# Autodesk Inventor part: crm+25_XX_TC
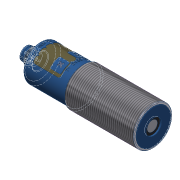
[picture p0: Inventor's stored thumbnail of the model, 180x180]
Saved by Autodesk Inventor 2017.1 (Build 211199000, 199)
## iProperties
Shininess: 20.0
Length Units: 11269
Angle Units: 11279
Time Units: 11290
Mass Units: 11283
Length Display Precision: 2
Angle Display Precision: 2
Company: Microsonic
Part Number: crm+25_XX_TC
Material: ABS Plastik
Document SubType Name: Modellieren
Description: mic+ 25 Sensor
Checked By: Alves
Created: 2005-08
Designer: Ohle
Manufacturer: Standard
Standards Organization: Custom
Appearance: Blau (himmelsblau)
Density: 0.0
Volumn: 0.0
Area: 0.0
PropertySet Name: Model Information
Control State: 0
Master: False
Checked Out: False
BESTELLNUMMER: mic+25/XX/TC
ME: ST
Title: mic+ 25 Sensor
Author: Ohle
Comments: keine Bemerkung
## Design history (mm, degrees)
revolve "Grundkörper" stored, may be unused: angle "d14" = 90 deg
workplane "Arbeitsebene1"
feature "Gewinde M30x1,5" dims "d79" = 10, "d80" = 0
feature "Gewinde M12x1" dims "d85" = 10, "d86" = 0
sketch "Skizze8"
  geometry: L1 (-94.032, 0)-(15.672, 0) reference; L2 (0, -19.965)-(0, 19.965) reference; L3 (-76.7, -13.9)-(-58.24, -13.9); L4 (-56.5, -12.16)-(-56.5, -3.843); L5 (-56.5, 3.843)-(-56.5, 12.16); L6 (-58.24, 13.9)-(-76.26, 13.9); L7 (-64.7, -11.7)-(-58.3, -11.7); L8 (-57.3, -10.7)-(-57.3, -3.9); L9 (-58.3, -2.9)-(-64.7, -2.9); L10 (-65.7, -3.9)-(-65.7, -10.7); L11 (-57.3, 4)-(-57.3, 10.7); L12 (-58.3, 11.7)-(-64.7, 11.7); L13 (-65.7, 10.7)-(-65.7, 4); L14 (-58, 2.107)-(-56.853, 3.081); L15 (-58, -2.1)-(-56.85, -3.083); L16 (-78, 12.16)-(-78, 5.023); L17 (-78, 1.577)-(-78, -0.577); L18 (-58.3, 3)-(-64.7, 3); L19 (-78, -4.023)-(-78, -6.827); L20 (-78, -10.273)-(-78, -12.6); L21 (-56.5, 0.383)-(-56.5, -0.377); A1 r 1.74 centre (-58.24, -12.16) between (-58.24, -13.9) and (-56.5, -12.16); A2 r 1.74 centre (-58.24, 12.16) between (-56.5, 12.16) and (-58.24, 13.9); A3 r 1.74 centre (-76.26, 12.16) between (-76.26, 13.9) and (-78, 12.16); A4 r 1 centre (-64.7, -3.9) between (-64.7, -2.9) and (-65.7, -3.9); A5 r 1 centre (-58.3, -3.9) between (-57.3, -3.9) and (-58.3, -2.9); A6 r 1 centre (-64.7, -10.7) between (-65.7, -10.7) and (-64.7, -11.7); A7 r 1 centre (-58.3, -10.7) between (-58.3, -11.7) and (-57.3, -10.7); A8 r 1 centre (-64.7, 4) between (-65.7, 4) and (-64.7, 3); A9 r 1 centre (-64.7, 10.7) between (-64.7, 11.7) and (-65.7, 10.7); A10 r 1 centre (-58.3, 4) between (-58.3, 3) and (-57.3, 4); A11 r 1 centre (-58.3, 10.7) between (-57.3, 10.7) and (-58.3, 11.7); A12 r 1 centre (-57.5, -3.843) between (-56.5, -3.843) and (-56.85, -3.083); A13 r 1 centre (-57.5, 3.843) between (-56.853, 3.081) and (-56.5, 3.843); A14 r 1.74 centre (-76.26, 5.023) between (-78, 5.023) and (-76.5, 3.3); A15 r 1.74 centre (-76.26, -10.273) between (-76.5, -8.55) and (-78, -10.273); A16 r 1.74 centre (-76.26, -6.827) between (-78, -6.827) and (-76.5, -8.55); A17 r 1.74 centre (-76.26, 1.577) between (-76.5, 3.3) and (-78, 1.577); A18 r 1.74 centre (-76.26, -0.577) between (-78, -0.577) and (-76.5, -2.3); A19 r 1.74 centre (-76.26, -4.023) between (-76.5, -2.3) and (-78, -4.023); A20 r 1.3 centre (-76.7, -12.6) between (-78, -12.6) and (-76.7, -13.9); A21 r 1.74 centre (-58.24, 0.383) between (-59.938, 0.003) and (-59.937, 0); A22 r 1.74 centre (-58.24, -0.377) between (-59.938, 0.003) and (-59.939, 0); A23 r 1.74 centre (-58.24, -0.377) between (-58, -2.1) and (-56.5, -0.377); A24 r 1.74 centre (-58.24, -0.377) between (-56.541, 0) and (-56.542, 0.003); A25 r 1.74 centre (-58.24, 0.383) between (-56.543, 0) and (-56.542, 0.003); A26 r 1.74 centre (-58.24, 0.383) between (-56.5, 0.383) and (-58, 2.107); 6 further points
  constraints: 52 point on circle, 38 end point, 37 tangent, 26 centre point, 14 point on line, 13 equal radius, 11 vertical alignment, 5 collinear, 5 horizontal alignment, 5 perpendicular, 4 parallel, 3 horizontal
  dimensions: "d98" = 56.5 distance between parallel lines of L2 L4; "d102" = 8.4 distance of point (-65.7, -11.7) point (-57.3, -11.7); "d103" = 9.2 distance between parallel lines of L10 L4; "d104" = 8.8 distance of point (-65.7, -2.9) point (-65.7, -11.7); "d105" = 2.9 distance between parallel lines of L1 L9; "d258" = 1 radius of A4; "d445" = 2.1 vertical distance of point (0, 0) L15.start; "d448" = 1 radius of A13; "d450" = 58 horizontal distance of point (0, 0) L14.start; "d452" = 21.5 distance between parallel lines of L16 L5; "d453" = 1.74 radius of A14; "d594" = 1.5 distance from line of L16 A14.end; "d596" = 3 distance from line of point (0, 0) L18; "d597" = 8.7 distance between parallel lines of L18 L12; "d619" = 13.9 distance from line of L3 point (0, 0); "d625" = 13.9 distance from line of point (0, 0) L6; "d630" = 3.3 vertical distance of point (0, 0) A14.end; "d644" = 5.35 distance from line of A15.start L3; "d645" = 1.3 radius of A20; "d782" = 2.3 vertical distance of A18.end point (0, 0); "d1000" = 49.4633 deg angle of L15 L2; "d1002" = 2.10658 distance from line of L1 L14.start; "d1003" = 1.74 radius of A26; "d1004" = 1.74 radius of A23; "d1005" = 1.74 radius of A25; "d1006" = 1.74 radius of A24
feature "Prägung Anzeige" sketch "Skizze8" dims "d4" = 11, "d9" = 15, "d10" = 14, "d11" = 6, "d12" = 5, "d32" = 1, "d33" = 1 (= d32), "d37" = 0.3, "d38" = 55.5, "d87" = 2, "d387" = 6, "d388" = 45 deg, "d389" = 13.5, "d390" = 0.5, "d391" = 0.5, "d396" = 45 deg, "d397" = 0.5, "d398" = 7.2, "d400" = 2, "d401" = 30 deg, "d402" = 5.175, "d403" = 0.2, "d404" = 1, "d405" = 10 deg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
feature "Prägung T1" dims "d4" = 11, "d9" = 15, "d10" = 14, "d11" = 6, "d12" = 5, "d32" = 1, "d33" = 1 (= d32), "d37" = 0.3, "d38" = 55.5, "d87" = 2, "d166" = 0.2, "d167" = 0, "d387" = 6, "d388" = 45 deg, "d389" = 13.5, "d390" = 0.5, "d391" = 0.5, "d396" = 45 deg, "d397" = 0.5, "d398" = 7.2, "d400" = 2, "d401" = 30 deg, "d402" = 5.175, "d403" = 0.2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
feature "Prägung D1" dims "d4" = 11, "d9" = 15, "d10" = 14, "d11" = 6, "d12" = 5, "d32" = 1, "d33" = 1 (= d32), "d37" = 0.3, "d38" = 55.5, "d87" = 2, "d387" = 6, "d388" = 45 deg, "d389" = 13.5, "d390" = 0.5, "d391" = 0.5, "d396" = 45 deg, "d397" = 0.5, "d398" = 7.2, "d400" = 2, "d401" = 30 deg, "d402" = 5.175, "d403" = 0.2, "d404" = 1, "d405" = 10 deg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
feature "Prägung D2" dims "d4" = 11, "d9" = 15, "d10" = 14, "d11" = 6, "d12" = 5, "d32" = 1, "d33" = 1 (= d32), "d37" = 0.3, "d38" = 55.5, "d87" = 2, "d387" = 6, "d388" = 45 deg, "d389" = 13.5, "d390" = 0.5, "d391" = 0.5, "d396" = 45 deg, "d397" = 0.5, "d398" = 7.2, "d400" = 2, "d401" = 30 deg, "d402" = 5.175, "d403" = 0.2, "d404" = 1, "d405" = 10 deg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
feature "Prägung T2" dims "d4" = 11, "d9" = 15, "d10" = 14, "d11" = 6, "d12" = 5, "d32" = 1, "d33" = 1 (= d32), "d37" = 0.3, "d38" = 55.5, "d87" = 2, "d387" = 6, "d388" = 45 deg, "d389" = 13.5, "d390" = 0.5, "d391" = 0.5, "d396" = 45 deg, "d397" = 0.5, "d398" = 7.2, "d400" = 2, "d401" = 30 deg, "d402" = 5.175, "d403" = 0.2, "d404" = 1, "d405" = 10 deg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
feature "Prägung cm mm" dims "d4" = 11, "d9" = 15, "d10" = 14, "d11" = 6, "d12" = 5, "d32" = 1, "d33" = 1 (= d32), "d37" = 0.3, "d38" = 55.5, "d87" = 2, "d387" = 6, "d388" = 45 deg, "d389" = 13.5, "d390" = 0.5, "d391" = 0.5, "d396" = 45 deg, "d397" = 0.5, "d398" = 7.2, "d400" = 2, "d401" = 30 deg, "d402" = 5.175, "d403" = 0.2, "d404" = 1, "d405" = 10 deg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
sketch "Skizze21" dims "d962" = 0.2, "d963" = 0.15, "d964" = 0.15, "d965" = 0.2, "d966" = 0.2, "d967" = 0.2
  geometry: L1 (-79, 2.922)-(-79, 3.135); L2 (-79, 3.135)-(-81, 3.863); L3 (-81, 3.863)-(-81, 3.65); L4 (-81, 3.65)-(-79, 2.922); 3 further points; 2 other entities
  constraints: 8 end point, 3 parallel, 2 vertical, 4 other
  dimensions: "d959" = 0.2 distance between parallel lines of L2 L4; "d960" = 2 horizontal distance of L2.end L1.end; "d961" = 70 deg angle of L4 L1; "d968" = 1 horizontal distance of point (-80.5, 2.5) point (-79.5, 4.2); "d969" = 0.5 distance from line of point (-80.5, 2.5) L3; "d970" = 1.7 vertical distance of point (-79.5, 4.2) point (-80.5, 2.5); "d971" = 1.15 vertical distance of point (-80.5, 2.5) L3.end; "d972" = 81 horizontal distance of point (0, 0) L2.end; "d973" = 2.5 vertical distance of point (0, 0) point (-80.5, 2.5)
feature "Prägung %" sketch "Skizze21" dims "d4" = 11, "d9" = 15, "d10" = 14, "d11" = 6, "d12" = 5, "d32" = 1, "d33" = 1 (= d32), "d37" = 0.3, "d38" = 55.5, "d87" = 2, "d387" = 6, "d388" = 45 deg, "d389" = 13.5, "d390" = 0.5, "d391" = 0.5, "d396" = 45 deg, "d397" = 0.5, "d398" = 7.2, "d400" = 2, "d401" = 30 deg, "d402" = 5.175, "d403" = 0.2, "d404" = 1, "d405" = 10 deg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
feature "Prägung X" dims "d4" = 11, "d9" = 15, "d10" = 14, "d11" = 6, "d12" = 5, "d32" = 1, "d33" = 1 (= d32), "d37" = 0.3, "d38" = 55.5, "d87" = 2, "d202" = 0.2, "d203" = 0, "d387" = 6, "d388" = 45 deg, "d389" = 13.5, "d390" = 0.5, "d391" = 0.5, "d396" = 45 deg, "d397" = 0.5, "d398" = 7.2, "d400" = 2, "d401" = 30 deg, "d402" = 5.175, "d403" = 0.2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
sketch "Skizze13"
  geometry: C1 r 4.999 at (0, 0) reference; 1 further point
hole "Bohrung1" sketch "Skizze13" at (0, 0) diameter "d267" = 9; stored, may be unused: countersink angle "d271" = 82 deg, drill point angle "d273" = 0 deg; dims "d268" = 6, "d269" = 4, "d270" = 2, "d272" = 8
sketch "Skizze14"
  geometry: L1 (-3.606, -3.606)-(3.692, 3.692); L2 (-3.873, 3.873)-(3.971, -3.971); L3 (0, -21)-(0, 21) reference; C1 r 0.75 at (0, 0); C2 r 0.75 at (2.121, -2.121); C3 r 0.75 at (2.121, 2.121); C4 r 0.75 at (-2.121, 2.121); C5 r 0.75 at (-2.121, -2.121); A1 r 3 centre (0, 0) between (-2.121, 2.121) and (2.121, 2.121); 1 further point
  constraints: 6 centre point, 6 point on line, 4 end point, 4 equal radius, 4 point on circle, 2 coincident
  dimensions: "d282" = 1.5 diameter of C4; "d283" = 6 diameter of A1; "d284" = 45 deg angle of L2 L3; "d285" = 45 deg angle of L3 L1
extrude "Pole" join sketch "Skizze14" distance "d286" = 7; taper "d287" = 0 deg
fillet "Abrundung Pole" dims "d288" = 0.75
sketch "Skizze15"
  geometry: L1 (0, -21)-(0, 21) reference; A1 r 4.5 centre (0, 0) between (4.472, -0.499) and (4.472, 0.499); A2 r 4.5 centre (0, 0) between (0, -4.5) and (0.499, -4.472) reference; A3 r 0.5 centre (0, -4.5) between (0.499, -4.472) and (-0.499, -4.472); 1 further point
  constraints: 7 point on circle, 2 centre point, 1 coincident, 1 point on line
  dimensions: "d289" = 9 diameter of A1; "d345" = 1 diameter of A3
extrude "Verdrehsicherung" join sketch "Skizze15" distance "d291" = 8; taper "d292" = 0 deg
fillet "Rundung2" dims "d1094" = 0.1
node "Volumenkörper1"
node "Volumenkörper"
node "Flächenkörper"
sketch "Skizze2"
  geometry: L1 (-114.412, 0)-(24.975, 0) reference; L2 (5, -3)-(5, 18); L3 (-94.5, 0)-(-94.5, 4.999) reference; L4 (-92.5, 5)-(-91.277, 5); L5 (-90.7, 6)-(-84, 6); L6 (-83.5, 6.5)-(-83.5, 12); L7 (-81.5, 14)-(-50.5, 14); L8 (-50.5, 14)-(-50.5, 14); L9 (-49.5, 15)-(4, 15); L10 (5, 13.2)-(5, 6); L11 (3.81, 0)-(-94.5, 0); L12 (4.5, 13.5)-(4.5, 13.5); L13 (4.5, 13.5)-(4.7, 13.5); L14 (-50.5, 14)-(-49.5, 15); L15 (3.8, 6)-(5, 6); L16 (4.5, 13.5)-(4.5, 14.5); L17 (4.5, 14.5)-(4, 15); L18 (-84, 6)-(-83.5, 6.5); L19 (-92.5, 5)-(-92.757, 5.148); L20 (-92.857, 5.175)-(-93.5, 5.175); L21 (-93.5, 5.175)-(-94.5, 4.999); L22 (-91.277, 5)-(-90.7, 6); L23 (3.8, 6)-(3.8, 4); L24 (3.8, 4)-(3.81, 4); L25 (3.81, 4)-(3.81, 0); A1 r 0.3 centre (4.7, 13.2) between (5, 13.2) and (4.7, 13.5); A2 r 2 centre (-81.5, 12) between (-81.5, 14) and (-83.5, 12); A3 r 0.2 centre (-92.857, 4.975) between (-92.757, 5.148) and (-92.857, 5.175); 5 further points
  constraints: 48 end point, 10 point on line, 6 perpendicular, 6 point on circle, 6 tangent, 5 parallel, 3 centre point, 2 collinear, 2 vertical
  dimensions: "d4" = 11 distance between parallel lines of L6 L3; "d9" = 15 distance between parallel lines of L9 L11; "d10" = 14 distance between parallel lines of L11 L7; "d11" = 6 distance between parallel lines of L11 L5; "d12" = 5 distance between parallel lines of L11 L4; "d32" = 1 distance of L8.end point (-50.5, 15); "d33" = 1 distance of L9.start point (-50.5, 15) (= d32); "d37" = 0.3 radius of A1; "d38" = 55.5 distance from line of L7.end L2; "d87" = 2 radius of A2; "d387" = 6 distance between parallel lines of L1 L15; "d388" = 45 deg angle of L16 L17; "d389" = 13.5 distance between parallel lines of L1 L13; "d390" = 0.5 distance between parallel lines of L16 L2; "d391" = 0.5 distance from line of L16 L9.end; "d396" = 45 deg angle of L6 L18; "d397" = 0.5 distance from line of L6.start L5; "d398" = 7.2 distance from line of L5.start L6; "d400" = 2 distance from line of L4.start L3; "d401" = 30 deg angle of L19 L4; "d402" = 5.175 distance between parallel lines of L1 L20; "d403" = 0.2 radius of A3; "d404" = 1 distance from line of L20.end L3; "d405" = 10 deg angle of L20 L21; "d593" = 60 deg angle of L5 L22; "d1092" = 1.2 distance between parallel lines of L23 L2; "d1093" = 0.01 distance between parallel lines of L25 L23; "d1095" = 4 distance of L24.end L11.start; "d1096" = 33 distance from line of L7.end L6
sketch "Skizze10"
  geometry: L1 (-80.7, -10.5)-(-80.7, -6.1); L2 (-80.7, -6.1)-(-70.7, -6.1); L3 (-70.7, -6.1)-(-70.7, -10.5); L4 (-70.7, -10.5)-(-80.7, -10.5); L5 (-70.7, -6.1)-(-70.7, -10.5); L6 (0, -12.639)-(0, 2.336) reference; L7 (-96.84, 0)-(16.14, 0) reference; L8 (-70.7, -4.7)-(-80.7, -4.7); L9 (-80.7, -4.7)-(-80.7, 0.196); L10 (-80.7, 0.196)-(-70.7, 0.196); L11 (-70.7, 0.196)-(-70.7, -4.7); 1 further point
  constraints: 2 collinear, 2 end point, 2 vertical, 4 other
  dimensions: "d424" = 80.7 distance from line of L1 point (0, 0); "d426" = 10.5 distance from line of point (0, 0) L4; "d461" = 10 distance between parallel lines of L1 L3; "d522" = 4.4 distance of L1.start L1.end; "d796" = 5.8 distance between parallel lines of L4 L8
sketch "Skizze11"
  geometry: L1 (-67.2, 0)-(11.2, 0) reference; L2 (0, -12.24)-(0, 11.84) reference; L3 (-56, -8.8)-(-56, 8.4); L4 (-56, 8.4)-(-52.713, 8.4); L5 (-52.713, 8.4)-(-52.713, -8.8); L6 (-52.713, -8.8)-(-56, -8.8); L7 (-52.713, 8.4)-(-52.713, -8.8); 1 further point
  constraints: 2 end point, 1 vertical, 2 other
  dimensions: "d467" = 56 distance from line of point (0, 0) L3; "d469" = 8.8 distance from line of point (0, 0) L6; "d476" = 8.4 distance from line of point (0, 0) L4
sketch "Skizze12"
  geometry: L1 (0, -14.725)-(0, 14.725) reference; L2 (-78.021, 0)-(13.004, 0) reference; L3 (-61.5, 10.518)-(-57.982, 7); L4 (-57.982, 7)-(-61.5, 3.482); L5 (-61.5, 3.482)-(-65.018, 7); L6 (-65.018, 7)-(-61.5, 10.518); L7 (-61.5, -3.482)-(-57.982, -7); L8 (-57.982, -7)-(-61.5, -10.518); L9 (-61.5, -10.518)-(-65.018, -7); L10 (-65.018, -7)-(-61.5, -3.482); 1 further point
  constraints: 5 vertical alignment, 2 perpendicular, 4 other
  dimensions: "d494" = 7 vertical distance of point (0, 0) L3.end; "d496" = 7 vertical distance of point (0, 0) L7.end; "d498" = 61.5 horizontal distance of point (0, 0) L4.end; "d504" = 90 deg angle of L7 L4
sketch "Skizze18"
  geometry: L1 (-52.713, -3.6)-(-56, -3.6); L2 (-56, -3.6)-(-56, 4.4); L3 (-56, 4.4)-(-52.713, 4.4); L4 (-52.713, 4.4)-(-52.713, -3.6); L5 (-52.713, 4.4)-(-52.713, -3.6); 1 further point
  constraints: 2 end point, 1 vertical, 2 other
  dimensions: "d668" = 3.6 vertical distance of L1.start point (0, 0); "d670" = 56 distance from line of L2 point (0, 0); "d671" = 8 distance between parallel lines of L1 L3
sketch "Skizze19"
  geometry: L1 (-52.713, 0.4)-(-56, 0.4); L2 (-56, 0.4)-(-56, 8.4); L3 (-56, 8.4)-(-52.713, 8.4); L4 (-52.713, 8.4)-(-52.713, 0.4); L5 (-52.713, 8.4)-(-52.713, 0.4); L6 (-52.713, 0.4)-(-56, 0.4); L7 (-56, 0.4)-(-56, 8.4); L8 (-52.713, 8.4)-(-52.713, 0.4); L9 (-52.713, 8.4)-(-52.713, 0.4); L10 (-56, 8.4)-(-52.713, 8.4); 2 further points
  constraints: 4 end point, 2 vertical, 1 coincident, 3 other
  dimensions: "d676" = 56 distance from line of L2 point (0, 0); "d677" = 8 distance between parallel lines of L1 L3; "d680" = 8 distance between parallel lines of L6 L10; "d701" = 0.4 distance from line of L1 point (0, 0)
sketch "Skizze20"
  geometry: L1 (-52.713, 5.7)-(-56, 5.7); L2 (-56, 5.7)-(-56, 11.6); L3 (-56, 11.6)-(-52.713, 11.6); L4 (-52.713, 11.6)-(-52.713, 5.7); L5 (-52.713, 11.6)-(-52.713, 5.7); L6 (-52.713, 5.7)-(-56, 5.7); L7 (-56, 5.7)-(-56, 13.7); L8 (-52.713, 13.7)-(-52.713, 5.7); L9 (-52.713, 13.7)-(-52.713, 5.7); L10 (-56, 13.7)-(-52.713, 13.7); L11 (-52.713, 5.7)-(-56, 5.7); L12 (-56, 5.7)-(-56, 13.7); L13 (-56, 13.7)-(-52.713, 13.7); L14 (-52.713, 13.7)-(-52.713, 5.7); L15 (-52.713, 5.7)-(-56, 5.7); L16 (-56, 5.7)-(-56, 13.7); L17 (-52.713, 13.7)-(-52.713, 5.7); L18 (-52.713, 13.7)-(-52.713, 5.7); L19 (-52.713, 13.7)-(-52.713, 5.7); L20 (-56, 13.7)-(-52.713, 13.7); 3 further points
  constraints: 8 end point, 4 vertical, 2 coincident, 1 collinear, 5 other
  dimensions: "d712" = 56 distance from line of L2 point (0, 0); "d715" = 5.7 distance from line of L1 point (0, 0); "d731" = 8 distance between parallel lines of L11 L13
other parameters: "d73" = -35
